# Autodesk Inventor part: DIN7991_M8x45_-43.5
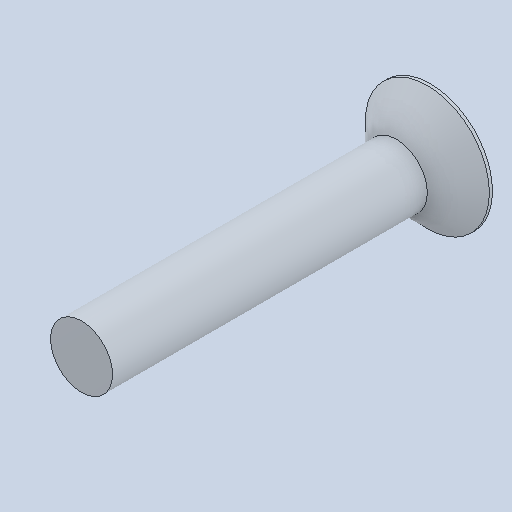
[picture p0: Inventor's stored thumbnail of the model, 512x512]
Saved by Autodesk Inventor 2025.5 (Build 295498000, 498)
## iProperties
Created: 2026-10
Part Number: DIN7991_M8x45_-43.5
Material: Genérico
Document SubType Name: Modeling
Designer: Luis M
Density: 1 g/cm^3
Appearance: Valor por defecto
Author: Luis M
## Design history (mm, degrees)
feature "Base1"
node "Sólido1"
